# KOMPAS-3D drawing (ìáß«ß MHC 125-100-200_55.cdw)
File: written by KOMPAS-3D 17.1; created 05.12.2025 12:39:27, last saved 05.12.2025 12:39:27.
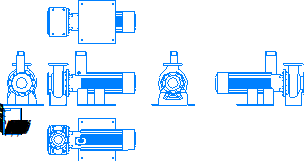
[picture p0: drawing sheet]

Sheet 1: A4, portrait

Title block, sheet 1: name: Насос MHC 125-100-200_55 / 55 кВт 3х380В; material: Сталь 10  ГОСТ 1050-88; mass: 362,08; sheets: 1; sheet format: A4

Views: Проекционный вид 2, Проекционный вид 3, Проекционный вид 4, Проекционный вид 5, Проекционный вид 6
Referenced files in \\adlc.lan\data\АДЛ_ПКД\3D-модели\ADL production\Насосы ГРАНПАМП\Насосы ГРАНПАМП серии МНС\KOMPAS 3D\: Насос MHC 125-100-200_55.m3d
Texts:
  Andrey
  АДЛ
Dimensions and other numbers on the sheet: 1:1; 1; 55 кВт 3х380В; 362,08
